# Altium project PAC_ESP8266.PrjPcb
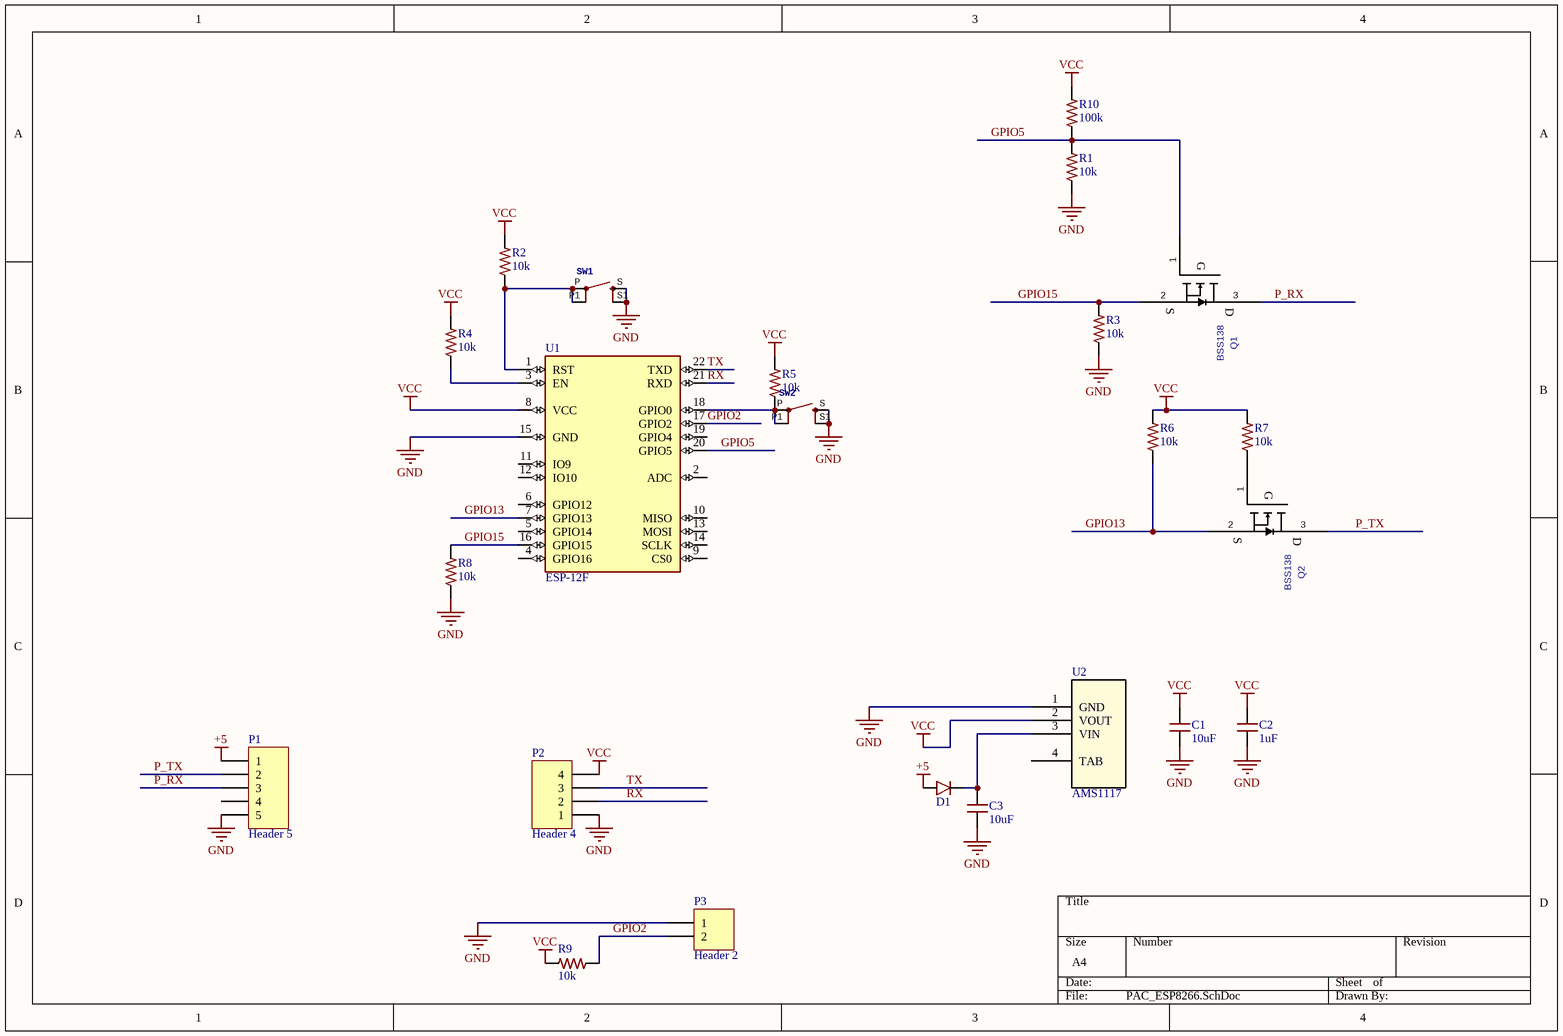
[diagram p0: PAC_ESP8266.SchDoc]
1 sheet, 23 parts. Net scope: global (net labels, ports and power ports of the same name join across sheets).

## Sheet PAC_ESP8266.SchDoc
size A4; SheetNumber: 1; SheetTotal: 1

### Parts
C1  10uF  [C0805]
C2  1uF  [C0805]
C3  10uF  [C0805]
D1  Diode_M7  [DO-214]  (value not drawn)
P1  Header 5  [HDR1X5]
P2  Header 4  [HDR1X4]
P3  Header 2  [HDR1X2]
Q1  BSS138  [SOT-23]
Q2  BSS138  [SOT-23]
R1  10k  [R0805W]
R2  10k  [R0805W]
R3  10k  [R0805W]
R4  10k  [R0805W]
R5  10k  [R0805W]
R6  10k  [R0805W]
R7  10k  [R0805W]
R8  10k  [R0805W]
R9  10k  [R0805W]
R10  100k  [R0805W]
SW1  10-XX-6MD  [BT6X6]  (value not drawn)
SW2  10-XX-6MD  [BT6X6]  (value not drawn)
U1  ESP-12F  [ESP-12F]
U2  AMS1117  [SOT-223]

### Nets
+5: D1.A P1.1
GND: C1.2 C2.2 C3.2 P1.5 P2.1 P3.1 R1.1 R3.1 R8.1 SW1.S SW1.S1 SW2.S SW2.S1 U1.15(GND) U2.1(GND)
VCC: C1.1 C2.1 P2.4 R2.2 R4.2 R5.2 R6.2 R7.2 R9.2 R10.2 U1.8(VCC) U2.2(VOUT)
GPIO2: P3.2 R9.1 U1.17(GPIO2)
GPIO5: Q1.1(G) R1.2 R10.1 U1.20(GPIO5)
GPIO13: Q2.2(S) R6.1 U1.7(GPIO13)
GPIO15: Q1.2(S) R3.2 R8.2 U1.16(GPIO15)
P_RX: P1.3 Q1.3(D)
P_TX: P1.2 Q2.3(D)
RX: P2.2 U1.21(RXD)
TX: P2.3 U1.22(TXD)
NetC3_1: C3.1 D1.C U2.3(VIN)
NetQ2_1: Q2.1(G) R7.1
NetR2_1: R2.1 SW1.P SW1.P1 U1.1(RST)
NetR4_1: R4.1 U1.3(EN)
NetR5_1: R5.1 SW2.P SW2.P1 U1.18(GPIO0)

Not connected (* = marked no-connect by the designer): P1 4; U1 2(ADC) 4(GPIO16) 5(GPIO14) 6(GPIO12) 9(CS0) 10(MISO) 11(IO9) 12(IO10) 13(MOSI) 14(SCLK) 19(GPIO4); U2 4(TAB)

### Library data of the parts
C1-C3 = C-USC0805
P1 = Header 5: Header, 5-Pin
P2 = Header 4: Header, 4-Pin
P3 = Header 2: Header, 2-Pin
Q1 Q2 = SI2302: Value: IRLZ44NPBF; C: Copyright (C) 2018 Accelerated Designs. All rights reserved; Vendor: Infineon; Built_By: EMA_UL_Team
R1-R10 = R-US_R0805W
SW1 SW2 = 10-XX-6MD: GateName_1: 1; SymbolName_1: TS2; DeviceName: -4.5SMD; DeviceSetName: 10-XX
U1 = ESP-12F: WiFi Module; MF: AI-Thinker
